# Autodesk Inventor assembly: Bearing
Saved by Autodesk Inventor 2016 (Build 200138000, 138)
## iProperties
Created: 2015-08
Part Number: Bearing
Document SubType Name: Assembly
Designer: Ugljesa
Mass: 72.9462 g
Surface Area: 85.1408 cm^2
Volume: 9.29251 cm^3
Density: 7.85 g/cm^3
ClientObjectVersion: 1
Author: Ugljesa
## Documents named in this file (2)
- C:\Users\Ugljesa\Desktop\Turbokompr\Assembly1\Design Accelerator\Bearing4.iam
- C:\Users\Ugljesa\Documents\Inventor\Content Center Files\R2016\en-US\BS 292 (V)\BS 292_ Part 1 - N 1005 - 25 x 47 x 12.ipt
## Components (1 placed, 1 different names)
1. BS 292: Part 1 (V) (Metric) N 1005 - 25 x 47 x 12:1
